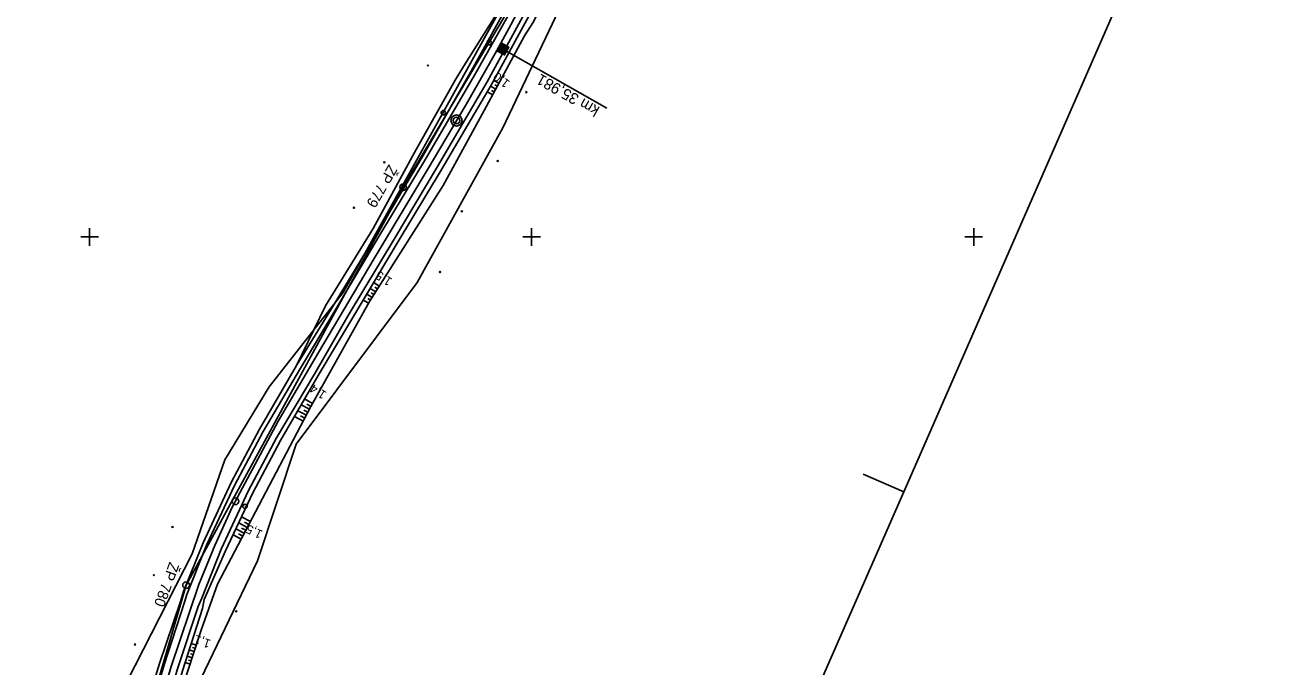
# Model space of a CAD drawing. Extents: x -806856 to -806332, y -1151642 to -1150946.
# Drawn here: x -806614.6 to -806331.6, y -1151297.3 to -1151152.1 of the extents above; entities that cross this region are included whole.
import ezdxf

# ---------------------------------------------------------------- set-up
doc = ezdxf.new("R2010")
doc.units = 0
for name, color, linetype in [('0381KM032-037P - Vrstva 1', 7, 'Continuous'), ('0381KM032-037P - Vrstva 27', 7, 'Continuous'), ('0381KM032-037P - Vrstva 3', 7, 'Continuous'), ('0381KM032-037P - Vrstva 4', 7, 'Continuous'), ('0381KM032-037P - Vrstva 48', 7, 'Continuous'), ('0381KM032-037P - Vrstva 49', 7, 'Continuous'), ('0381KM032-037P - Vrstva 7', 7, 'Continuous'), ('formát', 7, 'Continuous'), ('hran DP - hran DP', 7, 'Continuous'), ('krizky_1000 - Vrstva 1', 7, 'Continuous'), ('vyt_sit - ohrožené', 7, 'Continuous'), ('vyt_sit - polygon', 7, 'Continuous'), ('vyt_sit - stávající', 7, 'Continuous')]:
    doc.layers.add(name, color=color, linetype=linetype)

msp = doc.modelspace()

# ---------------------------------------------------------------- linework, layer by layer
at = {"layer": '0381KM032-037P - Vrstva 1'}
for points in [[(-806459.11, -1151042.15), (-806463.27, -1151055.58), (-806467.76, -1151068.75), (-806472.65, -1151081.99), (-806477.96, -1151095.43), (-806483.66, -1151108.91), (-806489.46, -1151121.74), (-806491.74, -1151126.53), (-806497.91, -1151139.08), (-806504.69, -1151152.02), (-806507.41, -1151157), (-806508.24, -1151158.47)], [(-806508.24, -1151158.47), (-806514.85, -1151170.04), (-806523.65, -1151184.88)], [(-806523.65, -1151184.88), (-806535.6, -1151204.92), (-806548.25, -1151226.13)], [(-806548.25, -1151226.13), (-806557.37, -1151241.69), (-806567.71, -1151261.13)], [(-806567.71, -1151261.13), (-806571.7, -1151269.85), (-806575.25, -1151278.64)], [(-806575.26, -1151278.66), (-806581.61, -1151297.45), (-806587.32, -1151317.2)]]:
    msp.add_lwpolyline(points, dxfattribs=at)
at = {"layer": '0381KM032-037P - Vrstva 27'}
msp.add_line((-806509.65, -1151156.05), (-806509.55, -1151156.05), dxfattribs=at)
msp.add_circle((-806509.6, -1151156.05), 0.5, dxfattribs=at)
at = {"layer": '0381KM032-037P - Vrstva 3'}
for p, q in [((-806507.53, -1151158.07), (-806507.7, -1151157.51)), ((-806507.07, -1151158.32), (-806507.44, -1151157.05)), ((-806507.41, -1151157), (-806483.02, -1151170.91)), ((-806506.6, -1151158.58), (-806507.19, -1151156.58)), ((-806506.14, -1151158.83), (-806506.93, -1151156.12)), ((-806505.88, -1151158.37), (-806506.47, -1151156.37)), ((-806505.63, -1151157.9), (-806506, -1151156.63)), ((-806505.37, -1151157.44), (-806505.54, -1151156.88))]:
    msp.add_line(p, q, dxfattribs=at)
msp.add_lwpolyline([(-806507.89, -1151157.87), (-806506.93, -1151156.12), (-806505.18, -1151157.08), (-806506.14, -1151158.83)], close=True, dxfattribs=at)
at = {"layer": '0381KM032-037P - Vrstva 4'}
for points in [[(-806449.56, -1151013.68), (-806449.62, -1151013.88), (-806452.81, -1151025.46), (-806457.3, -1151041.13), (-806462.78, -1151058.55), (-806470.34, -1151080.36), (-806477.94, -1151099.38), (-806485.55, -1151116.61), (-806493.04, -1151132.58), (-806500.67, -1151147.66), (-806510.08, -1151164.94), (-806521.27, -1151184.09), (-806531.11, -1151200.55)], [(-806448.21, -1151014.27), (-806448.22, -1151014.33), (-806451.54, -1151025.93), (-806456.14, -1151041.58), (-806461.64, -1151059.21), (-806469.17, -1151081.08), (-806476.72, -1151099.82), (-806484.37, -1151117.46), (-806491.94, -1151132.93), (-806500.08, -1151149.04), (-806509.16, -1151165.69), (-806520.46, -1151184.9), (-806530.22, -1151201.05)], [(-806453.41, -1151012), (-806457.09, -1151024.8), (-806461.35, -1151040.24), (-806466.6, -1151057.45), (-806474.53, -1151080.31), (-806481.65, -1151097.72), (-806488.93, -1151114.87), (-806496.54, -1151130.59), (-806504.49, -1151145.86), (-806513.59, -1151162.34)], [(-806452.41, -1151012.43), (-806452.61, -1151013.14), (-806455.7, -1151025.15), (-806460.24, -1151040.55), (-806465.79, -1151057.73), (-806473.74, -1151080.66), (-806480.83, -1151098.02), (-806488.21, -1151115.16), (-806495.76, -1151130.97), (-806503.39, -1151146.39), (-806512.71, -1151163.05)], [(-806513.59, -1151162.34), (-806524.74, -1151181.99), (-806534.73, -1151198.81)], [(-806512.71, -1151163.05), (-806524.03, -1151182.45), (-806534.14, -1151199.19)], [(-806534.73, -1151198.81), (-806545.37, -1151216.39), (-806553.18, -1151229.13), (-806561.58, -1151243.53), (-806567.96, -1151255.6), (-806574.3, -1151269.24), (-806578.76, -1151280.27), (-806579.4, -1151282.54), (-806584.22, -1151296.56), (-806589.48, -1151313.82), (-806594.95, -1151333.92), (-806600.1, -1151352.67), (-806608.81, -1151384.22), (-806613.08, -1151400.58)], [(-806534.14, -1151199.19), (-806544.55, -1151216.75), (-806552.31, -1151229.7), (-806560.71, -1151244.03), (-806567.24, -1151256.24), (-806573.52, -1151269.73), (-806577.97, -1151280.92), (-806578.5, -1151282.67), (-806583.15, -1151296.86), (-806588.26, -1151314.07), (-806594.08, -1151334.22), (-806599.38, -1151352.89), (-806608.02, -1151384.26), (-806612.6, -1151400.79)], [(-806531.11, -1151200.55), (-806541.48, -1151217.8), (-806549.08, -1151230.92), (-806557.69, -1151245.47), (-806564.05, -1151257.36), (-806570.21, -1151270.63), (-806574.62, -1151281.75), (-806575.45, -1151283.67), (-806580.1, -1151297.77), (-806585.12, -1151314.97), (-806590.56, -1151334.63), (-806595.8, -1151353.37), (-806604.61, -1151384.9), (-806609.41, -1151402.19)], [(-806530.22, -1151201.05), (-806540.66, -1151218.65), (-806548.31, -1151231.35), (-806556.78, -1151246.08), (-806563.07, -1151257.89), (-806569.22, -1151271.02), (-806574.1, -1151282.08), (-806574.48, -1151284.1), (-806578.97, -1151298.16), (-806583.83, -1151315.38), (-806589.34, -1151334.88), (-806594.45, -1151353.63), (-806603.42, -1151385.04), (-806608.69, -1151402.5)]]:
    msp.add_lwpolyline(points, dxfattribs=at)
at = {"layer": '0381KM032-037P - Vrstva 48'}
for p, q in [((-806508.1, -1151166.54), (-806509.29, -1151165.9)), ((-806508.45, -1151167.2), (-806509.06, -1151166.88)), ((-806507.39, -1151165.22), (-806508.56, -1151164.59)), ((-806507.74, -1151165.88), (-806508.33, -1151165.56)), ((-806508.81, -1151167.86), (-806510.05, -1151167.2)), ((-806535.27, -1151212.43), (-806536.5, -1151211.65)), ((-806534.47, -1151211.16), (-806535.73, -1151210.35)), ((-806534.87, -1151211.79), (-806535.49, -1151211.4)), ((-806536.85, -1151214.97), (-806538.08, -1151214.31)), ((-806536.08, -1151213.69), (-806537.27, -1151212.94)), ((-806536.48, -1151214.33), (-806537.06, -1151213.95)), ((-806535.67, -1151213.06), (-806536.28, -1151212.68)), ((-806549.55, -1151237.71), (-806551.38, -1151236.68)), ((-806549.91, -1151238.36), (-806550.83, -1151237.85)), ((-806551.66, -1151241.68), (-806553.65, -1151240.63)), ((-806550.96, -1151240.35), (-806552.9, -1151239.33)), ((-806551.31, -1151241.01), (-806552.29, -1151240.5)), ((-806550.26, -1151239.02), (-806552.15, -1151238.03)), ((-806550.61, -1151239.69), (-806551.57, -1151239.18)), ((-806563.63, -1151264.4), (-806565.62, -1151263.35)), ((-806565.02, -1151267.05), (-806566.9, -1151266.07)), ((-806564.33, -1151265.73), (-806566.26, -1151264.71)), ((-806564.67, -1151266.39), (-806565.63, -1151265.89)), ((-806563.97, -1151265.06), (-806564.96, -1151264.54)), ((-806565.72, -1151268.38), (-806567.54, -1151267.43)), ((-806565.37, -1151267.72), (-806566.3, -1151267.23)), ((-806576.33, -1151293.8), (-806577.46, -1151293.43)), ((-806576.56, -1151294.51), (-806577.15, -1151294.32)), ((-806575.86, -1151292.37), (-806577, -1151292)), ((-806576.1, -1151293.08), (-806576.71, -1151292.89)), ((-806577.26, -1151296.65), (-806578.37, -1151296.29)), ((-806576.79, -1151295.22), (-806577.92, -1151294.86)), ((-806577.02, -1151295.94), (-806577.6, -1151295.75))]:
    msp.add_line(p, q, dxfattribs=at)
at = {"layer": '0381KM032-037P - Vrstva 49'}
for p, q in [((-806523.3, -1151161.03), (-806523.66, -1151161.38)), ((-806523.66, -1151161.03), (-806523.3, -1151161.38)), ((-806501.03, -1151167.07), (-806501.39, -1151167.43)), ((-806501.39, -1151167.08), (-806501.03, -1151167.43)), ((-806533.51, -1151182.94), (-806533.15, -1151183.29)), ((-806533.15, -1151182.94), (-806533.5, -1151183.29)), ((-806507.48, -1151182.67), (-806507.84, -1151183.02)), ((-806507.84, -1151182.67), (-806507.48, -1151183.02)), ((-806540.04, -1151193.21), (-806540.39, -1151193.57)), ((-806540.39, -1151193.21), (-806540.03, -1151193.57)), ((-806515.61, -1151194.06), (-806515.96, -1151194.41)), ((-806515.96, -1151194.06), (-806515.61, -1151194.41)), ((-806520.55, -1151207.75), (-806520.9, -1151208.11)), ((-806520.9, -1151207.76), (-806520.54, -1151208.11)), ((-806581.43, -1151265.45), (-806581.07, -1151265.8)), ((-806581.07, -1151265.45), (-806581.42, -1151265.81)), ((-806585.29, -1151276.36), (-806585.64, -1151276.72)), ((-806585.64, -1151276.36), (-806585.29, -1151276.72)), ((-806566.67, -1151284.56), (-806567.02, -1151284.92)), ((-806567.02, -1151284.56), (-806566.66, -1151284.92)), ((-806589.55, -1151292.05), (-806589.91, -1151292.41)), ((-806589.91, -1151292.05), (-806589.55, -1151292.41))]:
    msp.add_line(p, q, dxfattribs=at)
for points in [[(-806448.2, -1151014.28), (-806448.22, -1151014.33), (-806451.54, -1151025.93), (-806456.14, -1151041.58), (-806461.64, -1151059.21), (-806469.17, -1151081.08), (-806476.72, -1151099.82), (-806484.37, -1151117.46), (-806491.94, -1151132.93), (-806500.08, -1151149.04), (-806509.16, -1151165.69), (-806520.46, -1151184.9), (-806530.22, -1151201.05)], [(-806446.83, -1151014.88), (-806447.16, -1151016), (-806450, -1151026.43), (-806453.97, -1151042.26), (-806459.11, -1151060.35), (-806468.36, -1151084.26), (-806475.1, -1151100.8), (-806483.46, -1151117.96), (-806490.37, -1151133.75), (-806499.76, -1151151.57), (-806501.59, -1151154.48), (-806510.73, -1151171.42), (-806520.01, -1151188.39)], [(-806496.54, -1151130.59), (-806505.32, -1151145.34), (-806515.42, -1151161.45), (-806517.29, -1151164.53), (-806526.47, -1151180.94), (-806535.85, -1151198.12)], [(-806520.01, -1151188.39), (-806536.66, -1151214.61), (-806549.93, -1151238.4), (-806571.09, -1151278.57), (-806574.7, -1151288.79), (-806577.92, -1151298.67), (-806582.99, -1151315.77), (-806588.39, -1151335.12), (-806593.7, -1151353.88), (-806600.16, -1151386.57)], [(-806535.85, -1151198.12), (-806546.61, -1151215.57), (-806553.18, -1151229.13), (-806561.58, -1151243.53), (-806567.96, -1151255.6), (-806574.3, -1151269.24), (-806578.76, -1151280.27), (-806579.4, -1151282.54), (-806584.22, -1151296.56), (-806589.48, -1151313.82), (-806594.95, -1151333.92), (-806600.1, -1151352.67), (-806608.81, -1151384.22), (-806614.6, -1151399.91)], [(-806530.22, -1151201.05), (-806540.66, -1151218.65), (-806548.31, -1151231.35), (-806556.78, -1151246.08), (-806563.07, -1151257.89), (-806569.22, -1151271.02), (-806574.1, -1151282.08)], [(-806574.1, -1151282.08), (-806574.48, -1151284.1), (-806578.97, -1151298.16), (-806583.83, -1151315.38), (-806589.34, -1151334.88), (-806594.45, -1151353.63), (-806603.42, -1151385.04), (-806608.48, -1151402.59)]]:
    msp.add_lwpolyline(points, dxfattribs=at)
at = {"layer": '0381KM032-037P - Vrstva 7'}
for p, q in [((-806520.04, -1151171.89), (-806519.94, -1151171.89)), ((-806564.89, -1151260.99), (-806564.79, -1151260.99))]:
    msp.add_line(p, q, dxfattribs=at)
for centre, radius in [((-806519.99, -1151171.89), 0.5), ((-806517, -1151173.66), 1.25), ((-806517, -1151173.66), 0.752), ((-806567.02, -1151259.83), 0.75), ((-806564.84, -1151260.99), 0.5)]:
    msp.add_circle(centre, radius, dxfattribs=at)
at = {"layer": 'formát'}
for p, q in [((-806331.63, -1151065.3), (-806415.83, -1151257.68)), ((-806424.99, -1151253.67), (-806415.83, -1151257.68)), ((-806424.99, -1151253.67), (-806415.83, -1151257.68)), ((-806415.83, -1151257.68), (-806500.03, -1151450.06))]:
    msp.add_line(p, q, dxfattribs=at)
at = {"layer": 'hran DP - hran DP'}
for p, q in [((-806485.36, -1151130.76), (-806506.53, -1151175.36)), ((-806542.64, -1151212.58), (-806506.25, -1151146.99)), ((-806506.53, -1151175.36), (-806525.91, -1151210.3)), ((-806525.91, -1151210.3), (-806553.28, -1151246.87)), ((-806559.38, -1151233.91), (-806542.64, -1151212.58)), ((-806569.42, -1151250.48), (-806559.38, -1151233.91)), ((-806553.28, -1151246.87), (-806561.98, -1151273.31)), ((-806576.79, -1151271.69), (-806569.42, -1151250.48)), ((-806591.51, -1151300.57), (-806576.79, -1151271.69)), ((-806561.98, -1151273.31), (-806579.39, -1151309.52))]:
    msp.add_line(p, q, dxfattribs=at)
at = {"layer": 'krizky_1000 - Vrstva 1'}
for points in [[(-806600, -1151198), (-806600, -1151202)], [(-806500, -1151198), (-806500, -1151202)], [(-806400, -1151198), (-806400, -1151202)], [(-806602, -1151200), (-806598, -1151200)], [(-806502, -1151200), (-806498, -1151200)], [(-806402, -1151200), (-806398, -1151200)]]:
    msp.add_lwpolyline(points, dxfattribs=at)
at = {"layer": 'vyt_sit - ohrožené'}
msp.add_line((-806529.11, -1151188.76), (-806529.01, -1151188.76), dxfattribs=at)
msp.add_circle((-806529.06, -1151188.76), 0.756, dxfattribs=at)
at = {"layer": 'vyt_sit - polygon'}
for p, q in [((-806529.06, -1151188.76), (-806470.95, -1151090.83)), ((-806578.18, -1151278.81), (-806529.06, -1151188.76)), ((-806613.33, -1151399.56), (-806578.18, -1151278.81))]:
    msp.add_line(p, q, dxfattribs=at)
at = {"layer": 'vyt_sit - stávající'}
msp.add_line((-806578.22, -1151278.81), (-806578.12, -1151278.81), dxfattribs=at)
msp.add_circle((-806578.18, -1151278.81), 0.756, dxfattribs=at)

# ---------------------------------------------------------------- texts
at = {"layer": '0381KM032-037P - Vrstva 3'}
msp.add_text('km 35,981', height=2.5, rotation=150.2693, dxfattribs=at).set_placement((-806484.41, -1151170.73))
at = {"layer": '0381KM032-037P - Vrstva 48'}
for s, rotation, p in [('1,0', 142.0922, (-806504.79, -1151164.89)), ('1,5', 147.9162, (-806531.38, -1151209.56)), ('1,4', 147.0433, (-806546.24, -1151235.23)), ('1,5', 154.8905, (-806560.68, -1151266.6)), ('1,1', 160.7839, (-806572.42, -1151291.27))]:
    msp.add_text(s, height=2, rotation=rotation, dxfattribs=at).set_placement(p)
at = {"layer": 'vyt_sit - ohrožené'}
msp.add_text('ŽP 779', height=2.4, rotation=240, dxfattribs=at).set_placement((-806532.3, -1151183.48))
at = {"layer": 'vyt_sit - stávající'}
msp.add_text('ŽP 780', height=2.4, rotation=250, dxfattribs=at).set_placement((-806581.91, -1151273.42))

doc.saveas('drawing.dxf')
